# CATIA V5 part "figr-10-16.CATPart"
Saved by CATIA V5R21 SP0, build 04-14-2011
Part number: Part1
Bounding box of the stored display mesh (mm): x -29.811 to 29.811, y 0 to 29.811, z -21.213 to 21.213
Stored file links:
  D:\CATIA V5R21 E-RESOURCES\CATIA-V5R21\catia-v5r21-prt\c10-catia-v5r20-prt\c10-catia-v5r21-figr-10-16.CATPart
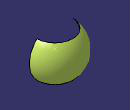
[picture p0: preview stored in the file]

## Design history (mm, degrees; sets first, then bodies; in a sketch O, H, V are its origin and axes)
Set1
  Point1: (0, 0, 0)
  Sphere1: Center Point1, Radius 30, Para1 -45, Para3 0, Para4 180
Body1 (main body)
